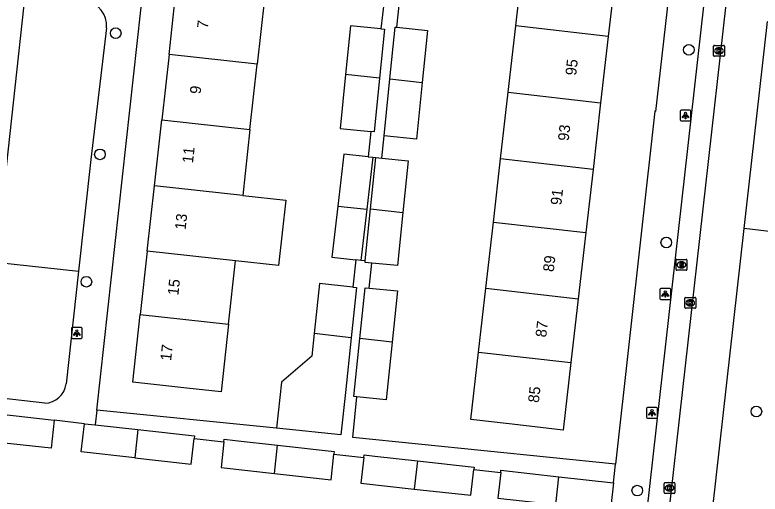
# Model space of a CAD drawing. Extents: x 161928 to 163055, y 386475 to 387428.
# Drawn here: x 162242.7 to 162311.1, y 387064.4 to 387108.4 of the extents above; entities that cross this region are included whole.
import ezdxf

# ---------------------------------------------------------------- set-up
doc = ezdxf.new("R2010")
doc.units = 0
for name, color, linetype in [('IMGEO_Boom', 7, 'Continuous'), ('IMGEO_Kolk', 7, 'Continuous'), ('IMGEO_Lichtpunt', 7, 'Continuous'), ('IMGEO_Pand', 7, 'Continuous'), ('IMGEO_Pand_nummerreeks', 7, 'Continuous'), ('IMGEO_Parkeervlak_open', 7, 'Continuous'), ('IMGEO_Rijbaan_lokaal_open', 7, 'Continuous'), ('IMGEO_Rioolput', 7, 'Continuous'), ('IMGEO_Voetpad_open', 7, 'Continuous')]:
    doc.layers.add(name, color=color, linetype=linetype)

msp = doc.modelspace()

# ---------------------------------------------------------------- linework, layer by layer
at = {"layer": 'IMGEO_Boom'}
for centre in [(162251.977, 387106.73), (162304.599, 387105.195), (162250.532, 387095.588), (162302.528, 387087.49), (162249.289, 387083.881), (162310.798, 387071.962), (162299.864, 387064.689)]:
    msp.add_circle(centre, 0.489, dxfattribs=at)
at = {"layer": 'IMGEO_Kolk'}
for p, q in [((162306.867, 387104.673), (162306.867, 387105.525)), ((162306.942, 387105.599), (162307.794, 387105.599)), ((162307.355, 387105.379), (162307.38, 387105.379)), ((162307.868, 387105.525), (162307.868, 387104.673)), ((162307.378, 387104.819), (162307.353, 387104.819)), ((162307.794, 387104.599), (162306.942, 387104.599)), ((162304.228, 387081.517), (162304.228, 387082.369)), ((162304.303, 387082.443), (162305.155, 387082.443)), ((162304.716, 387082.223), (162304.741, 387082.223)), ((162305.229, 387082.369), (162305.229, 387081.517)), ((162305.155, 387081.443), (162304.303, 387081.443)), ((162304.739, 387081.663), (162304.714, 387081.663)), ((162302.327, 387064.5), (162302.327, 387065.352)), ((162302.402, 387065.426), (162303.254, 387065.426)), ((162302.815, 387065.206), (162302.84, 387065.206)), ((162303.328, 387065.352), (162303.328, 387064.5)), ((162303.254, 387064.426), (162302.402, 387064.426)), ((162302.838, 387064.646), (162302.813, 387064.646))]:
    msp.add_line(p, q, dxfattribs=at)
for points in [[(162306.867, 387104.673), (162306.867, 387105.525)], [(162306.942, 387105.599), (162307.794, 387105.599)], [(162307.868, 387105.525), (162307.868, 387104.673)], [(162307.188, 387105.299), (162307.311, 387105.299), (162307.311, 387105.148), (162307.441, 387105.299), (162307.605, 387105.299), (162307.459, 387105.148), (162307.612, 387104.899), (162307.46, 387104.899), (162307.375, 387105.063), (162307.311, 387104.996), (162307.311, 387104.899), (162307.188, 387104.899), (162307.188, 387105.299)], [(162307.794, 387104.599), (162306.942, 387104.599)], [(162304.228, 387081.517), (162304.228, 387082.369)], [(162304.303, 387082.443), (162305.155, 387082.443)], [(162304.549, 387082.143), (162304.672, 387082.143), (162304.672, 387081.992), (162304.802, 387082.143), (162304.966, 387082.143), (162304.82, 387081.992), (162304.973, 387081.743), (162304.821, 387081.743), (162304.736, 387081.907), (162304.672, 387081.84), (162304.672, 387081.743), (162304.549, 387081.743), (162304.549, 387082.143)], [(162305.229, 387082.369), (162305.229, 387081.517)], [(162305.155, 387081.443), (162304.303, 387081.443)], [(162302.327, 387064.5), (162302.327, 387065.352)], [(162302.402, 387065.426), (162303.254, 387065.426)], [(162302.648, 387065.126), (162302.771, 387065.126), (162302.771, 387064.975), (162302.901, 387065.126), (162303.065, 387065.126), (162302.919, 387064.975), (162303.072, 387064.726), (162302.92, 387064.726), (162302.835, 387064.89), (162302.771, 387064.823), (162302.771, 387064.726), (162302.648, 387064.726), (162302.648, 387065.126)], [(162303.328, 387065.352), (162303.328, 387064.5)], [(162303.254, 387064.426), (162302.402, 387064.426)]]:
    msp.add_lwpolyline(points, dxfattribs=at)
for centre, start, end in [((162306.944, 387105.523), 91.55205, 178.44795), ((162306.944, 387105.523), 91.55205, 178.44795), ((162307.792, 387105.523), 1.55205, 88.44795), ((162307.792, 387105.523), 1.55205, 88.44795), ((162306.944, 387104.675), 181.55205, 268.44795), ((162306.944, 387104.675), 181.55205, 268.44795), ((162307.792, 387104.675), 271.55205, 358.44795), ((162307.792, 387104.675), 271.55205, 358.44795), ((162304.305, 387082.367), 91.55205, 178.44795), ((162304.305, 387082.367), 91.55205, 178.44795), ((162305.153, 387082.367), 1.55205, 88.44795), ((162305.153, 387082.367), 1.55205, 88.44795), ((162304.305, 387081.519), 181.55205, 268.44795), ((162304.305, 387081.519), 181.55205, 268.44795), ((162305.153, 387081.519), 271.55205, 358.44795), ((162305.153, 387081.519), 271.55205, 358.44795), ((162302.404, 387065.35), 91.55205, 178.44795), ((162302.404, 387065.35), 91.55205, 178.44795), ((162303.252, 387065.35), 1.55205, 88.44795), ((162303.252, 387065.35), 1.55205, 88.44795), ((162302.404, 387064.502), 181.55205, 268.44795), ((162302.404, 387064.502), 181.55205, 268.44795), ((162303.252, 387064.502), 271.55205, 358.44795), ((162303.252, 387064.502), 271.55205, 358.44795)]:
    msp.add_arc(centre, 0.0765, start, end, dxfattribs=at)
for centre, major_axis, ratio, start_param, end_param in [((162307.354, 387105.099), (-0.387, 0.002), 0.722429, 4.712389, 7.853982), ((162307.379, 387105.099), (-0.39, 0.002), 0.717154, 1.570796, 4.712389), ((162304.715, 387081.943), (-0.387, 0.002), 0.722429, 4.712389, 7.853982), ((162304.74, 387081.943), (-0.39, 0.002), 0.717154, 1.570796, 4.712389), ((162302.814, 387064.926), (-0.387, 0.002), 0.722429, 4.712389, 7.853982), ((162302.839, 387064.926), (-0.39, 0.002), 0.717154, 1.570796, 4.712389)]:
    msp.add_ellipse(centre, major_axis=major_axis, ratio=ratio, start_param=start_param, end_param=end_param, dxfattribs=at)
at = {"layer": 'IMGEO_Lichtpunt'}
for p, q in [((162303.795, 387099.565), (162303.795, 387098.758)), ((162303.795, 387099.565), (162303.795, 387098.758)), ((162304.697, 387099.66), (162303.889, 387099.66)), ((162304.697, 387099.66), (162303.889, 387099.66)), ((162304.791, 387098.758), (162304.791, 387099.565)), ((162304.791, 387098.758), (162304.791, 387099.565)), ((162303.889, 387098.664), (162304.697, 387098.664)), ((162303.889, 387098.664), (162304.697, 387098.664)), ((162301.941, 387083.162), (162301.941, 387082.355)), ((162301.941, 387083.162), (162301.941, 387082.355)), ((162302.843, 387083.257), (162302.035, 387083.257)), ((162302.843, 387083.257), (162302.035, 387083.257)), ((162302.937, 387082.355), (162302.937, 387083.162)), ((162302.937, 387082.355), (162302.937, 387083.162)), ((162302.035, 387082.261), (162302.843, 387082.261)), ((162302.035, 387082.261), (162302.843, 387082.261)), ((162247.906, 387079.569), (162247.906, 387078.762)), ((162247.906, 387079.569), (162247.906, 387078.762)), ((162248.808, 387079.664), (162248, 387079.664)), ((162248.808, 387079.664), (162248, 387079.664)), ((162248.902, 387078.762), (162248.902, 387079.569)), ((162248.902, 387078.762), (162248.902, 387079.569)), ((162248, 387078.668), (162248.808, 387078.668)), ((162248, 387078.668), (162248.808, 387078.668)), ((162300.723, 387072.237), (162300.723, 387071.43)), ((162300.723, 387072.237), (162300.723, 387071.43)), ((162301.625, 387072.332), (162300.817, 387072.332)), ((162301.625, 387072.332), (162300.817, 387072.332)), ((162301.719, 387071.43), (162301.719, 387072.237)), ((162301.719, 387071.43), (162301.719, 387072.237)), ((162300.817, 387071.336), (162301.625, 387071.336)), ((162300.817, 387071.336), (162301.625, 387071.336))]:
    msp.add_line(p, q, dxfattribs=at)
for points in [[(162304.169, 387099.229), (162304.208, 387099.201), (162304.02, 387098.939), (162303.982, 387098.966), (162304.169, 387099.229)], [(162304.381, 387099.201), (162304.419, 387099.228), (162304.606, 387098.966), (162304.567, 387098.938), (162304.381, 387099.201)], [(162304.271, 387099.181), (162304.318, 387099.181), (162304.318, 387098.859), (162304.271, 387098.859), (162304.271, 387099.181)], [(162302.315, 387082.826), (162302.354, 387082.798), (162302.166, 387082.536), (162302.128, 387082.563), (162302.315, 387082.826)], [(162302.527, 387082.798), (162302.565, 387082.825), (162302.752, 387082.563), (162302.713, 387082.535), (162302.527, 387082.798)], [(162302.417, 387082.778), (162302.464, 387082.778), (162302.464, 387082.456), (162302.417, 387082.456), (162302.417, 387082.778)], [(162248.28, 387079.233), (162248.319, 387079.205), (162248.131, 387078.943), (162248.093, 387078.97), (162248.28, 387079.233)], [(162248.382, 387079.185), (162248.429, 387079.185), (162248.429, 387078.863), (162248.382, 387078.863), (162248.382, 387079.185)], [(162248.492, 387079.205), (162248.53, 387079.232), (162248.717, 387078.97), (162248.678, 387078.942), (162248.492, 387079.205)], [(162301.097, 387071.901), (162301.136, 387071.873), (162300.948, 387071.611), (162300.91, 387071.638), (162301.097, 387071.901)], [(162301.199, 387071.853), (162301.246, 387071.853), (162301.246, 387071.531), (162301.199, 387071.531), (162301.199, 387071.853)], [(162301.309, 387071.873), (162301.347, 387071.9), (162301.534, 387071.638), (162301.495, 387071.61), (162301.309, 387071.873)]]:
    msp.add_lwpolyline(points, dxfattribs=at)
for centre in [(162304.294, 387099.363), (162302.44, 387082.96), (162248.405, 387079.367), (162301.222, 387072.035)]:
    msp.add_circle(centre, 0.0994, dxfattribs=at)
for centre, start, end in [((162303.889, 387099.565), 90, 180), ((162303.889, 387099.565), 90, 180), ((162304.697, 387099.565), 0, 90), ((162304.697, 387099.565), 0, 90), ((162303.889, 387098.758), 180, 270), ((162303.889, 387098.758), 180, 270), ((162304.697, 387098.758), 270, 0), ((162304.697, 387098.758), 270, 360), ((162302.035, 387083.162), 90, 180), ((162302.035, 387083.162), 90, 180), ((162302.843, 387083.162), 0, 90), ((162302.843, 387083.162), 0, 90), ((162302.035, 387082.355), 180, 270), ((162302.035, 387082.355), 180, 270), ((162302.843, 387082.355), 270, 0), ((162302.843, 387082.355), 270, 360), ((162248, 387079.569), 90, 180), ((162248, 387079.569), 90, 180), ((162248.808, 387079.569), 0, 90), ((162248.808, 387079.569), 0, 90), ((162248, 387078.762), 180, 270), ((162248, 387078.762), 180, 270), ((162248.808, 387078.762), 270, 0), ((162248.808, 387078.762), 270, 360), ((162300.817, 387072.237), 90, 180), ((162300.817, 387072.237), 90, 180), ((162301.625, 387072.237), 0, 90), ((162301.625, 387072.237), 0, 90), ((162300.817, 387071.43), 180, 270), ((162300.817, 387071.43), 180, 270), ((162301.625, 387071.43), 270, 0), ((162301.625, 387071.43), 270, 360)]:
    msp.add_arc(centre, 0.0946, start, end, dxfattribs=at)
at = {"layer": 'IMGEO_Pand'}
for points in [[(162288.709, 387107.398), (162289.395, 387113.41)], [(162297.887, 387112.441), (162297.201, 387106.428)], [(162256.876, 387104.764), (162257.542, 387110.801)], [(162265.641, 387109.907), (162264.974, 387103.87)], [(162276.318, 387107.128), (162273.524, 387107.409), (162273.074, 387102.935)], [(162276.318, 387107.128), (162276.643, 387107.095), (162276.19, 387102.591)], [(162277.157, 387102.521), (162277.645, 387107.285), (162277.803, 387107.269)], [(162277.803, 387107.269), (162280.618, 387106.98), (162280.126, 387102.182)], [(162288.012, 387101.294), (162288.709, 387107.398)], [(162297.201, 387106.428), (162288.709, 387107.398)], [(162297.201, 387106.428), (162296.504, 387100.324)], [(162256.876, 387104.764), (162256.212, 387098.751)], [(162264.974, 387103.87), (162256.876, 387104.764)], [(162264.309, 387097.857), (162264.974, 387103.87)], [(162273.074, 387102.935), (162272.575, 387097.974), (162275.388, 387097.691)], [(162276.19, 387102.591), (162273.074, 387102.935)], [(162276.19, 387102.591), (162275.694, 387097.66), (162275.388, 387097.691)], [(162276.622, 387097.296), (162277.157, 387102.521)], [(162280.126, 387102.182), (162279.595, 387096.991), (162276.622, 387097.296)], [(162277.157, 387102.521), (162280.126, 387102.182)], [(162287.313, 387095.17), (162288.012, 387101.294)], [(162288.012, 387101.294), (162296.504, 387100.324)], [(162296.504, 387100.324), (162295.805, 387094.201)], [(162255.544, 387092.697), (162256.212, 387098.751)], [(162256.212, 387098.751), (162264.309, 387097.857)], [(162264.309, 387097.857), (162263.64, 387091.803)], [(162275.154, 387095.364), (162272.925, 387095.619), (162272.377, 387090.838)], [(162275.581, 387095.315), (162275.034, 387090.545)], [(162275.154, 387095.364), (162275.581, 387095.315)], [(162275.375, 387090.591), (162275.857, 387095.305)], [(162275.857, 387095.305), (162276.413, 387095.248)], [(162276.413, 387095.248), (162278.829, 387095.001), (162278.344, 387090.252)], [(162286.65, 387089.363), (162287.313, 387095.17)], [(162295.805, 387094.201), (162287.313, 387095.17)], [(162295.805, 387094.201), (162295.142, 387088.393)], [(162254.881, 387086.696), (162255.544, 387092.697)], [(162263.64, 387091.803), (162255.544, 387092.697)], [(162263.64, 387091.803), (162267.602, 387091.365), (162266.94, 387085.364), (162262.98, 387085.802)], [(162272.377, 387090.838), (162271.837, 387086.14), (162274.026, 387085.889)], [(162272.377, 387090.838), (162275.034, 387090.545)], [(162275.034, 387090.545), (162274.493, 387085.835)], [(162274.884, 387085.795), (162275.375, 387090.591)], [(162275.375, 387090.591), (162278.344, 387090.252)], [(162278.344, 387090.252), (162277.843, 387085.36), (162275.495, 387085.601)], [(162285.957, 387083.286), (162286.65, 387089.363)], [(162286.65, 387089.363), (162295.142, 387088.393)], [(162295.142, 387088.393), (162294.449, 387082.317)], [(162254.881, 387086.696), (162254.238, 387080.871)], [(162262.98, 387085.802), (162254.881, 387086.696)], [(162262.337, 387079.978), (162262.98, 387085.802)], [(162274.493, 387085.835), (162274.026, 387085.889)], [(162275.495, 387085.601), (162274.871, 387085.665), (162274.884, 387085.795)], [(162273.758, 387083.382), (162270.688, 387083.709), (162270.199, 387079.111)], [(162273.758, 387083.382), (162274.094, 387083.346), (162273.603, 387078.736)], [(162274.393, 387078.658), (162274.872, 387083.337), (162275.259, 387083.297)], [(162275.259, 387083.297), (162277.845, 387083.032), (162277.362, 387078.319)], [(162285.287, 387077.415), (162285.957, 387083.286)], [(162285.957, 387083.286), (162294.449, 387082.317)], [(162294.449, 387082.317), (162293.779, 387076.446)], [(162262.337, 387079.978), (162261.652, 387073.769), (162258.523, 387074.114), (162253.553, 387074.663), (162254.238, 387080.871)], [(162254.238, 387080.871), (162262.337, 387079.978)], [(162270.199, 387079.111), (162269.978, 387077.034), (162267.197, 387074.654), (162266.748, 387070.428)], [(162273.603, 387078.736), (162273.07, 387073.717), (162272.654, 387069.8), (162266.748, 387070.428)], [(162273.603, 387078.736), (162270.199, 387079.111)], [(162274.121, 387073.32), (162273.849, 387073.348), (162274.393, 387078.658)], [(162277.362, 387078.319), (162276.822, 387073.043), (162274.121, 387073.32)], [(162277.362, 387078.319), (162274.393, 387078.658)], [(162293.779, 387076.446), (162293.072, 387070.251), (162288.105, 387070.818), (162284.58, 387071.22), (162285.287, 387077.415)], [(162285.287, 387077.415), (162293.779, 387076.446)], [(162246.341, 387071.169), (162246.055, 387068.577), (162240.889, 387069.147)], [(162241.177, 387071.739), (162246.341, 387071.169)], [(162253.723, 387067.696), (162248.818, 387068.238), (162249.106, 387070.839)], [(162249.106, 387070.839), (162250.101, 387070.729)], [(162250.101, 387070.729), (162254.012, 387070.297)], [(162254.012, 387070.297), (162253.723, 387067.696)], [(162254.012, 387070.297), (162259.204, 387069.724), (162259.176, 387069.468)], [(162253.723, 387067.696), (162258.916, 387067.123), (162259.176, 387069.468)], [(162261.914, 387069.165), (162261.653, 387066.804), (162266.558, 387066.262)], [(162261.914, 387069.165), (162261.941, 387069.405), (162262.936, 387069.295), (162266.847, 387068.863)], [(162266.558, 387066.262), (162266.847, 387068.863)], [(162266.847, 387068.863), (162272.039, 387068.29), (162272.012, 387068.047)], [(162266.558, 387066.262), (162271.751, 387065.689), (162272.012, 387068.047)], [(162274.752, 387067.744), (162274.489, 387065.371), (162279.394, 387064.829)], [(162274.752, 387067.744), (162274.777, 387067.972), (162275.772, 387067.862), (162279.683, 387067.43)], [(162279.683, 387067.43), (162279.394, 387064.829)], [(162279.683, 387067.43), (162284.875, 387066.857), (162284.849, 387066.625)], [(162279.394, 387064.829), (162284.587, 387064.256), (162284.849, 387066.625)], [(162287.329, 387066.347), (162287.353, 387066.563), (162292.667, 387065.968)], [(162287.329, 387066.347), (162287.066, 387064.003), (162292.38, 387063.408), (162292.667, 387065.968)]]:
    msp.add_lwpolyline(points, dxfattribs=at)
at = {"layer": 'IMGEO_Parkeervlak_open'}
for points in [[(162311.81, 387107.808), (162314.374, 387107.497), (162312.248, 387088.459), (162309.685, 387088.77)], [(162240.937, 387085.688), (162248.567, 387084.852)]]:
    msp.add_lwpolyline(points, dxfattribs=at)
at = {"layer": 'IMGEO_Rijbaan_lokaal_open'}
for points in [[(162309.861, 387125.998), (162300.517, 387042.959)], [(162243.864, 387112.171), (162240.937, 387085.688)], [(162309.685, 387088.77), (162311.81, 387107.808)], [(162301.966, 387020.029), (162309.685, 387088.77)]]:
    msp.add_lwpolyline(points, dxfattribs=at)
at = {"layer": 'IMGEO_Rioolput'}
for p, q in [((162303.422, 387085.01), (162303.422, 387085.862)), ((162303.497, 387085.936), (162304.349, 387085.936)), ((162303.91, 387085.716), (162303.935, 387085.716)), ((162304.423, 387085.862), (162304.423, 387085.01)), ((162304.349, 387084.936), (162303.497, 387084.936)), ((162303.933, 387085.156), (162303.908, 387085.156))]:
    msp.add_line(p, q, dxfattribs=at)
for points in [[(162303.422, 387085.01), (162303.422, 387085.862)], [(162303.497, 387085.936), (162304.349, 387085.936)], [(162304.011, 387085.634), (162303.759, 387085.636), (162303.759, 387085.236)], [(162303.937, 387085.555), (162303.883, 387085.555), (162303.883, 387085.474)], [(162304.423, 387085.862), (162304.423, 387085.01)], [(162304.349, 387084.936), (162303.497, 387084.936)], [(162303.759, 387085.236), (162303.883, 387085.236), (162303.883, 387085.398), (162303.894, 387085.398)], [(162303.883, 387085.474), (162303.935, 387085.474)], [(162303.941, 387085.369), (162304.012, 387085.236), (162304.152, 387085.236), (162304.087, 387085.362)]]:
    msp.add_lwpolyline(points, dxfattribs=at)
for centre, radius, start, end in [((162303.499, 387085.86), 0.0765, 91.55205, 178.44795), ((162303.499, 387085.86), 0.0765, 91.55205, 178.44795), ((162303.943, 387085.459), 0.0964, 77.00612, 93.18647), ((162303.957, 387085.516), 0.0378, 276.66336, 79.67722), ((162304.01, 387085.524), 0.109, 350.36119, 89.41601), ((162304.347, 387085.86), 0.0765, 1.55205, 88.44795), ((162304.347, 387085.86), 0.0765, 1.55205, 88.44795), ((162303.499, 387085.012), 0.0765, 181.55205, 268.44795), ((162303.499, 387085.012), 0.0765, 181.55205, 268.44795), ((162303.893, 387085.345), 0.0533, 26.02933, 88.69889), ((162303.919, 387085.663), 0.19, 274.7715, 282.96867), ((162304.008, 387085.524), 0.112, 277.58423, 350.98172), ((162303.992, 387085.309), 0.108, 29.51342, 73.79051), ((162304.347, 387085.012), 0.0765, 271.55205, 358.44795), ((162304.347, 387085.012), 0.0765, 271.55205, 358.44795)]:
    msp.add_arc(centre, radius, start, end, dxfattribs=at)
for centre, major_axis, ratio, start_param, end_param in [((162303.909, 387085.436), (-0.387, 0.002), 0.722429, 4.712389, 7.853982), ((162303.934, 387085.436), (-0.39, 0.002), 0.717154, 1.570796, 4.712389)]:
    msp.add_ellipse(centre, major_axis=major_axis, ratio=ratio, start_param=start_param, end_param=end_param, dxfattribs=at)
at = {"layer": 'IMGEO_Voetpad_open'}
for points in [[(162250.249, 387072.075), (162256.634, 387130.312)], [(162304.407, 387124.9), (162301.553, 387099.54), (162301.491, 387099.547), (162297.867, 387067.105)], [(162298.684, 387044.352), (162307.745, 387125.029)], [(162276.612, 387109.687), (162276.318, 387107.128)], [(162277.803, 387107.269), (162278.008, 387109.271)], [(162251.144, 387107.229), (162249.696, 387095.101), (162248.567, 387084.852)], [(162275.388, 387097.691), (162275.154, 387095.364)], [(162276.413, 387095.248), (162276.622, 387097.296)], [(162275.581, 387095.315), (162275.857, 387095.305)], [(162274.026, 387085.889), (162273.758, 387083.382)], [(162274.884, 387085.795), (162274.493, 387085.835)], [(162275.259, 387083.297), (162275.495, 387085.601)], [(162248.567, 387084.852), (162247.425, 387074.489)], [(162245.458, 387072.725), (162239.58, 387073.412)], [(162297.867, 387067.105), (162273.737, 387069.581), (162274.121, 387073.32)], [(162250.249, 387072.075), (162250.101, 387070.729)], [(162266.748, 387070.428), (162250.249, 387072.075)], [(162249.106, 387070.839), (162246.341, 387071.169)], [(162259.176, 387069.468), (162261.914, 387069.165)], [(162272.012, 387068.047), (162274.752, 387067.744)], [(162297.677, 387065.408), (162297.867, 387067.105)], [(162284.849, 387066.625), (162287.329, 387066.347)], [(162292.667, 387065.968), (162297.677, 387065.408)], [(162297.677, 387065.408), (162295.188, 387043.126)]]:
    msp.add_lwpolyline(points, dxfattribs=at)
for centre, radius, start, end in [((162248.836, 387107.405), 2.315, 355.63954, 80.89247), ((162245.421, 387074.745), 2.02, 271.04729, 352.72404)]:
    msp.add_arc(centre, radius, start, end, dxfattribs=at)

# ---------------------------------------------------------------- texts
at = {"layer": 'IMGEO_Pand_nummerreeks'}
for s, rotation, p in [('7', 83.70128, (162260.434, 387107.11)), ('95', 83.48933, (162294.25, 387102.798)), ('9', 83.70128, (162259.77, 387101.095)), ('93', 83.48933, (162293.564, 387096.783)), ('11', 83.70128, (162259.069, 387094.737)), ('91', 83.48933, (162292.89, 387090.88)), ('13', 83.7034, (162258.392, 387088.61)), ('89', 83.48933, (162292.191, 387084.753)), ('15', 83.70128, (162257.728, 387082.595)), ('87', 83.48933, (162291.504, 387078.738)), ('17', 83.70128, (162257.064, 387076.58)), ('85', 83.48933, (162290.818, 387072.723))]:
    msp.add_text(s, height=1, rotation=rotation, dxfattribs=at).set_placement(p)

doc.saveas('drawing.dxf')
